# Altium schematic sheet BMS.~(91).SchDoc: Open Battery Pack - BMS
size A3; Date: 26/03/2019; Author: Morgane Vallée - Samuel Lesueur; Revision: 1.0; SheetNumber: 1; SheetTotal: 5
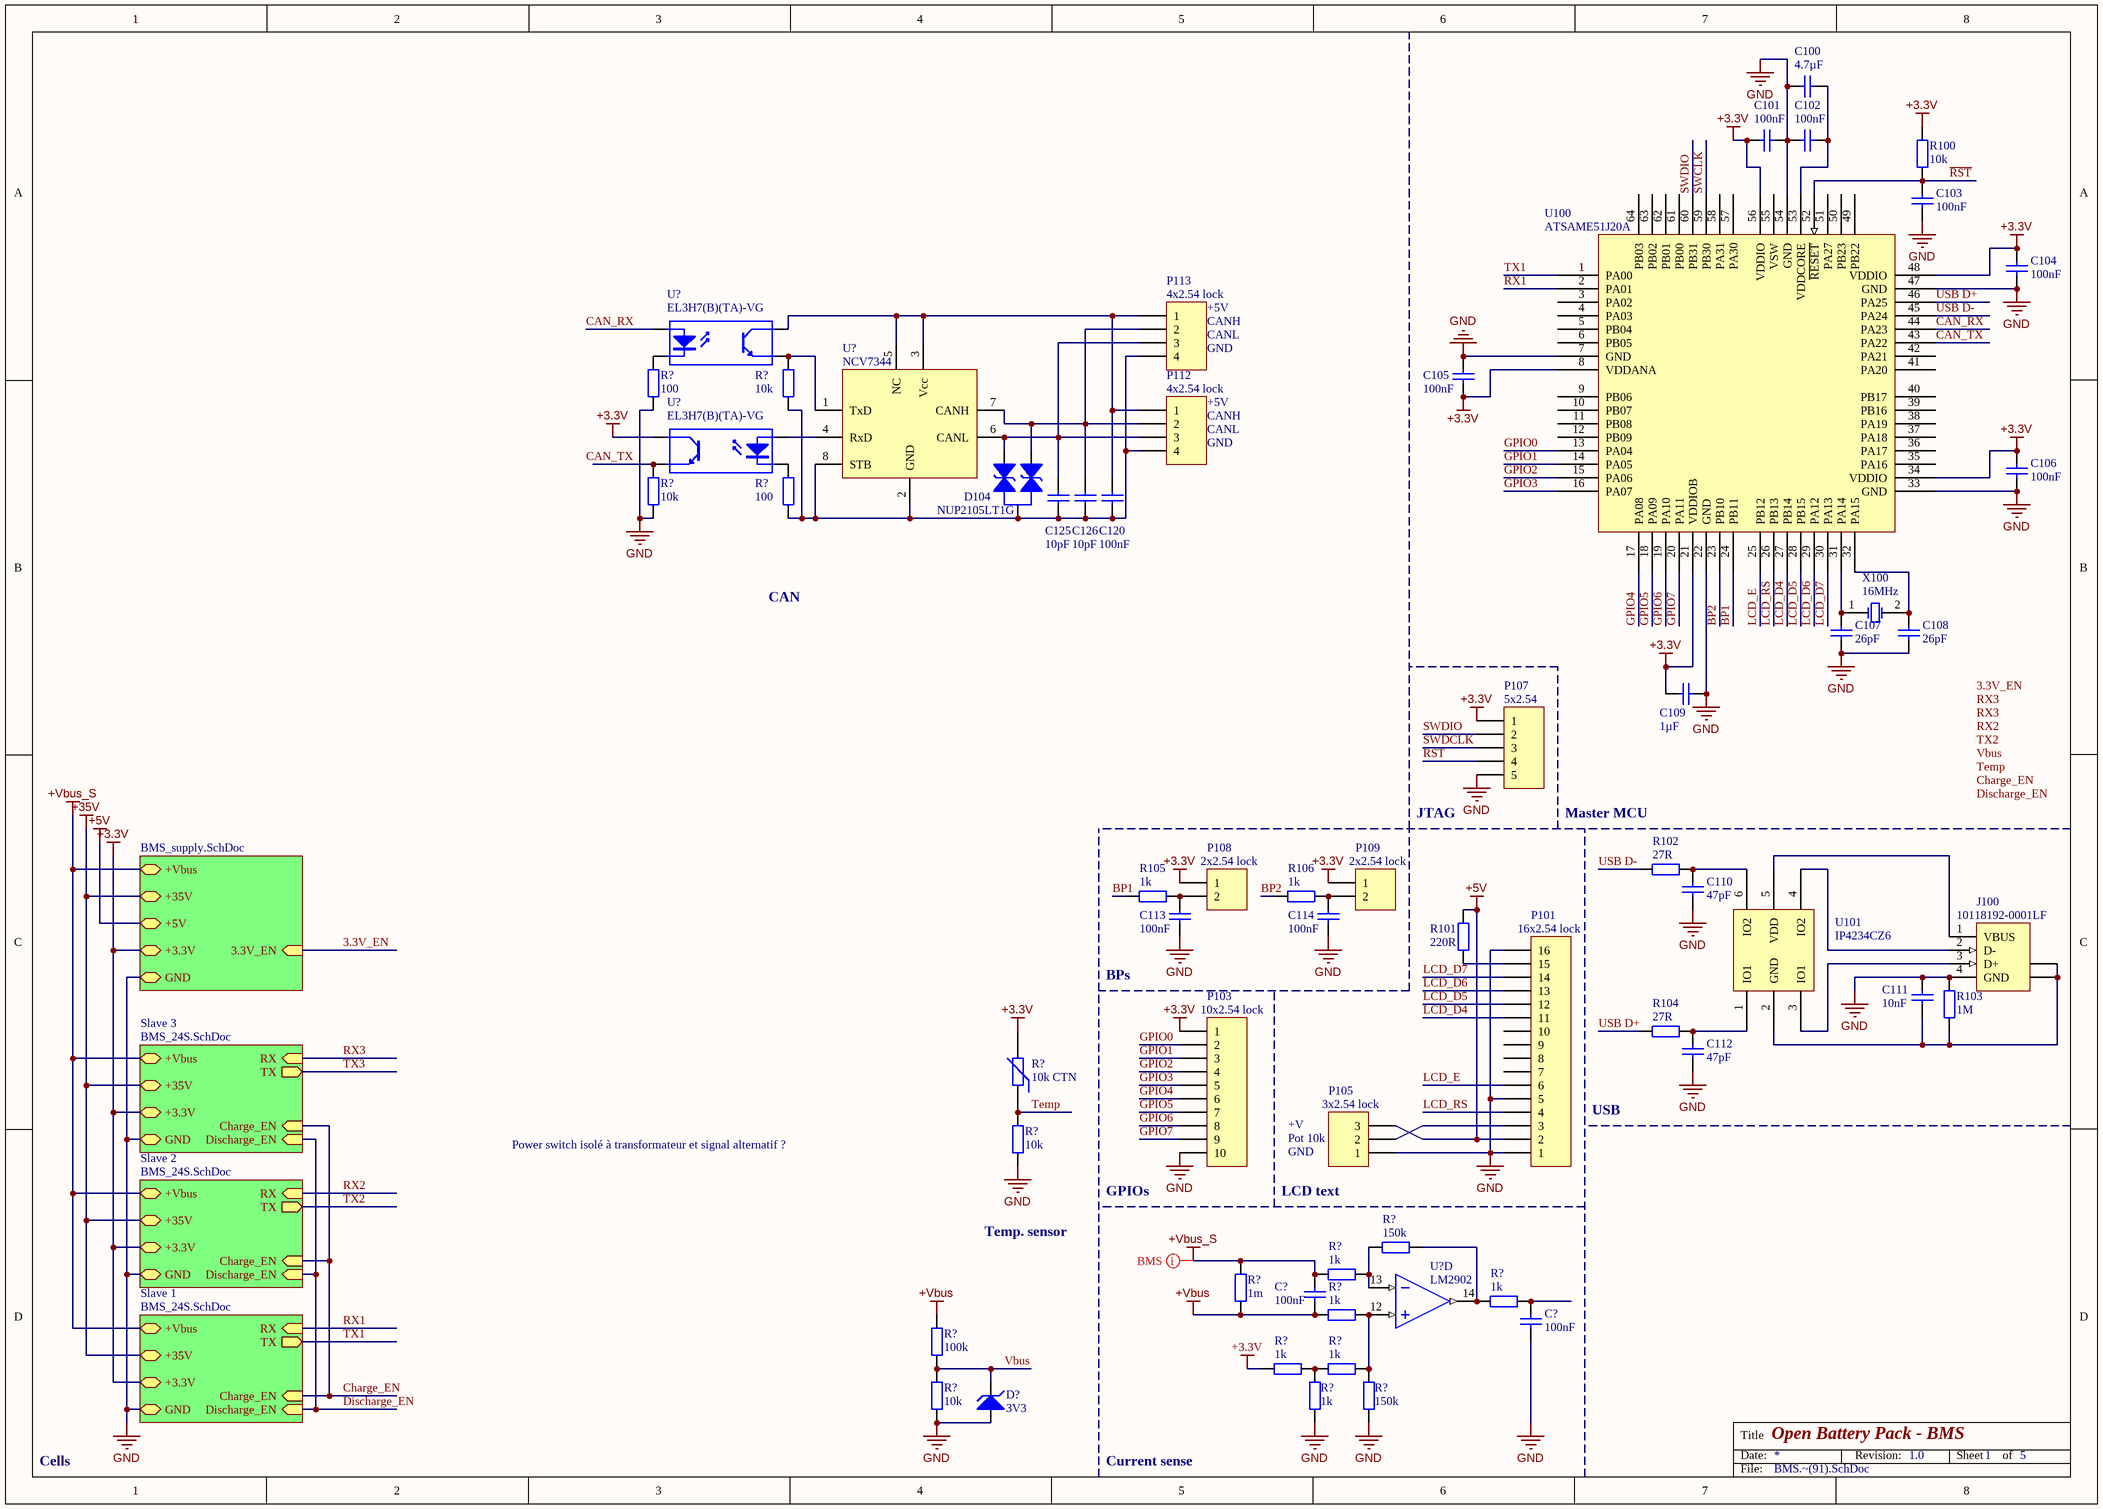
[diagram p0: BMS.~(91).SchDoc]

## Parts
(Parts that share a designator on the sheet are numbered #1, #2 ... from top to bottom, then left to right.)
C100  4.7µF  [C0603]
C101  100nF  [C0603]
C102  100nF  [C0603]
C103  100nF  [C0603]
C104  100nF  [C0603]
C105  100nF  [C0603]
C106  100nF  [C0603]
C107  26pF  [C0603]
C108  26pF  [C0603]
C109  1µF  [C0603]
C110  47pF  [C0603]
C111  10nF  [C0603]
C112  47pF  [C0603]
C113  100nF  [C0603]
C114  100nF  [C0603]
C120  100nF  [C0603]
C125  10pF  [C0603]
C126  10pF  [C0603]
C?#1  100nF  [C0603]
C?#2  100nF  [C0603]
D104  NUP2105LT1G  [DIODES SOT-23-3]
D?  3V3  [DIODE-0.7]
J100  10118192-0001LF  [FCI USB 10118193-0001LF]
P101  16x2.54 lock  [HDR1X16]
P103  10x2.54 lock  [MOLEX KK 0022272101]
P105  3x2.54 lock  [MOLEX KK 0022272031]
P107  5x2.54  [HDR1X5]
P108  2x2.54 lock  [MOLEX KK 0022272021]
P109  2x2.54 lock  [MOLEX KK 0022272021]
P112  4x2.54 lock  [MOLEX SDA-70553-4PIN]
P113  4x2.54 lock  [MOLEX SDA-70553-4PIN]
R100  10k  [R0603]
R101  220R  [R0603]
R102  27R  [R0603]
R103  1M  [R0603]
R104  27R  [R0603]
R105  1k  [R0603]
R106  1k  [R0603]
R?#1  10k  [R0603]
R?#2  100  [R0603]
R?#3  10k  [R0603]
R?#4  100  [R0603]
R?#5  10k CTN  [NTC 0402/1005]
R?#6  10k  [R0603]
R?#7  1k  [R0603]
R?#8  150k  [R0603]
R?#9  1m  [R1206]
R?#10  1k  [R0603]
R?#11  100k  [R0603]
R?#12  1k  [R0603]
R?#13  10k  [R0603]
R?#14  1k  [R0603]
R?#15  1k  [R0603]
R?#16  1k  [R0603]
R?#17  150k  [R0603]
U100  ATSAME51J20A  [TQFP-64N]
U101  IP4234CZ6  [VISHAY TSOP-6 MO-193C]
U?#1  EL3H7(B)(TA)-VG  [OPTO_EL3H7-G]
U?#2  EL3H7(B)(TA)-VG  [OPTO_EL3H7-G]
U?#3  NCV7344  [ON SEMI SO-8]
U?#4  LM2902  [Atmel SO-14 14S1]  (part D of 5)
X100  16MHz  [ABRACON ABLS]

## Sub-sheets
Slave 1 = BMS_24S.SchDoc: +Vbus, +3.3V, GND, +35V, RX (in), TX (out), Charge_EN (in), Discharge_EN (in)
Slave 2 = BMS_24S.SchDoc: +Vbus, +3.3V, GND, +35V, RX (in), TX (out), Charge_EN (in), Discharge_EN (in)
Slave 3 = BMS_24S.SchDoc: +Vbus, +3.3V, GND, +35V, RX (in), TX (out), Charge_EN (in), Discharge_EN (in)
? = BMS_supply.SchDoc: +Vbus, +3.3V, GND, +35V, +5V, 3.3V_EN (in)

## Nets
+3.3V: C101.2 C104.2 C105.1 C106.2 C109.2 P103.1 P107.1 P108.1 P109.1 R100.2 R?#5.2 R?#14.2 U100.8(VDDANA) U100.21(VDDIOB) U100.34(VDDIO) U100.48(VDDIO) U100.56(VDDIO) U?#2.4(C) ; sheet Slave 1/+3.3V, sheet /+3.3V, sheet Slave 2/+3.3V, sheet Slave 3/+3.3V
+5V: P101.2 P105.3 R101.2 ; sheet /+5V
+35V: sheet Slave 1/+35V, sheet /+35V, sheet Slave 2/+35V, sheet Slave 3/+35V
+Vbus: C?#1.2 R?#9.1 R?#11.1 R?#12.2
+Vbus_S: C?#1.1 R?#7.1 R?#9.2 ; sheet Slave 1/+Vbus, sheet /+Vbus, sheet Slave 2/+Vbus, sheet Slave 3/+Vbus
GND: C100.2 C101.1 C102.2 C103.1 C104.1 C105.2 C106.1 C107.1 C108.1 C109.1 C110.1 C111.2 C112.1 C113.1 C114.1 C?#2.2 D?.1(A) J100.4(GND) P101.1 P101.5 P101.16 P103.10 P105.1 P107.5 R103.1 R?#2.1 R?#3.2 R?#6.2 R?#13.2 R?#15.2 R?#17.1 U100.7(GND) U100.22(GND) U100.33(GND) U100.47(GND) U100.54(GND) ; sheet Slave 1/GND, sheet /GND, sheet Slave 2/GND, sheet Slave 3/GND
BP1: R105.1 U100.24(PB11)
BP2: R106.1 U100.23(PB10)
CAN_RX: U100.44(PA23) U?#1.1(A)
CAN_TX: U100.43(PA22)
Charge_EN: sheet Slave 1/Charge_EN, sheet Slave 2/Charge_EN, sheet Slave 3/Charge_EN
Discharge_EN: sheet Slave 1/Discharge_EN, sheet Slave 2/Discharge_EN, sheet Slave 3/Discharge_EN
GPIO0: P103.2 U100.13(PA04)
GPIO1: P103.3 U100.14(PA05)
GPIO2: P103.4 U100.15(PA06)
GPIO3: P103.5 U100.16(PA07)
GPIO4: P103.6 U100.17(PA08)
GPIO5: P103.7 U100.18(PA09)
GPIO6: P103.8 U100.19(PA10)
GPIO7: P103.9 U100.20(PA11)
LCD_D4: P101.11 U100.27(PB14)
LCD_D5: P101.12 U100.28(PB15)
LCD_D6: P101.13 U100.29(PA12)
LCD_D7: P101.14 U100.30(PA13)
LCD_E: P101.6 U100.25(PB12)
LCD_RS: P101.4 U100.26(PB13)
~{RST}: C103.2 P107.4 R100.1 U100.52(~{RESET})
RX1: U100.2(PA01) ; sheet Slave 1/RX
SWCLK: U100.59(PB30)
SWDCLK: P107.3
SWDIO: P107.2 U100.60(PB31)
Temp: R?#5.1 R?#6.1
TX1: U100.1(PA00) ; sheet Slave 1/TX
USB D+: R104.1 U100.46(PA25)
USB D-: R102.1 U100.45(PA24)
Vbus: D?.2(K) R?#11.2 R?#13.1
NetC100_1: C100.1 C102.1 U100.53(VDDCORE)
NetC107_2: C107.2 U100.31(PA14) X100.1(OSC1)
NetC108_2: C108.2 U100.32(PA15) X100.2(OSC2)
NetC110_2: C110.2 R102.2 U101.6(IO2)
NetC111_1: C111.1 J100.5(SHLD) J100.6(SHLD) R103.2 U101.2(GND)
NetC112_2: C112.2 R104.2 U101.1(IO1)
NetC113_2: C113.2 P108.2 R105.2
NetC114_2: C114.2 P109.2 R106.2
NetC120_1: C120.1 C125.1 C126.1 D104.3 P112.4 P113.4 R?#1.2 R?#4.1 U?#3.2(GND) U?#3.8(STB)
NetC120_2: C120.2 P112.1 P113.1 U?#1.4(C) U?#3.3(Vcc) U?#3.5(NC)
NetC125_2: C125.2 D104.2 P112.3 P113.3 U?#3.6(CANL)
NetC126_2: C126.2 D104.1 P112.2 P113.2 U?#3.7(CANH)
NetC?#2_1: C?#2.1 R?#10.1
NetJ100_1: J100.1(VBUS) U101.5(VDD)
NetJ100_2: J100.2(D-) U101.4(IO2)
NetJ100_3: J100.3(D+) U101.3(IO1)
NetP101_3: P101.3 P105.2
NetP101_15: P101.15 R101.1
NetR?#1_1: R?#1.1 U?#1.3(E) U?#3.1(TxD)
NetR?#2_2: R?#2.2 U?#1.2(K)
NetR?#3_1: R?#3.1 U?#2.3(E)
NetR?#4_2: R?#4.2 U?#2.2(K)
NetR?#7_2: R?#7.2 R?#8.2 U?#4.13(IN-)
NetR?#8_1: R?#8.1 R?#10.2 U?#4.14(OUT)
NetR?#12_1: R?#12.1 R?#16.1 R?#17.2 U?#4.12(IN+)
NetR?#14_1: R?#14.1 R?#15.1 R?#16.2
NetU?#2_1: U?#2.1(A) U?#3.4(RxD)

Not connected (* = marked no-connect by the designer): P101 7 8 9 10; U100 3(PA02) 4(PA03) 5(PB04) 6(PB05) 9(PB06) 10(PB07) 11(PB08) 12(PB09) 35(PA16) 36(PA17) 37(PA18) 38(PA19) 39(PB16) 40(PB17) 41(PA20) 42(PA21) 49(PB22) 50(PB23) 51(PA27) 55(VSW) 57(PA30) 58(PA31) 61(PB00) 62(PB01) 63(PB02) 64(PB03)

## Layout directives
net class BMS: +Vbus_S

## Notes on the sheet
- (near P113) +5V
- (near P113) CANH
- (near P113) CANL
- (near P113) GND
- +5V
- (near P112) CANH
- (near P112) CANL
- (near P112) GND
- CAN
- JTAG
- Master MCU
- BPs
- +V
- USB
- Power switch isolé à transformateur et signal alternatif ?
- (near P105) Pot 10k
- GND
- Temp. sensor
- GPIOs
- LCD text
- Cells
- Current sense
- Labels drawn without touching a wire or pin: 3.3V_EN, CAN_TX, Charge_EN, Discharge_EN, RX2, RX3, Temp, TX2, Vbus

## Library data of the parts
C100-C114 C120 C125 C126 C?#1 C?#2 = Cap: Capacitor
D104 = Dual Line TVS
D? = Diode Zener
J100 = 1-353576-1: USB 1.1, Right Angle, SMT, A Type, Receptacle, 4 Position, White; pin to pad: 4>5 5>S 6>S
P101 = Header 16: Header, 16-Pin
P103 = Header 10: Header, 10-Pin
P105 = Header 3: Header, 3-Pin
P107 = Header 5: Header, 5-Pin
P108 P109 = Header 2: Header, 2-Pin
P112 P113 = Header 4H: Header, 4-Pin, Right Angle
R100-R106 R?#1-R?#4 R?#6-R?#17 = Res2: Resistor
R?#5 = Res Varistor: Varistor (Voltage-Sensitive Resistor)
U101 = IP4234CZ6: Single USB 2.0 ESD protection to IEC 61000-4-2 level 4
U?#1 U?#2 = Optoisolator1
U?#3 = NCV7344: High Speed Low PowerCAN, CAN FD Transceiver
U?#4 = LM2902: Low-power quad operational amplifiers
X100 = XTAL: Crystal Oscillator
